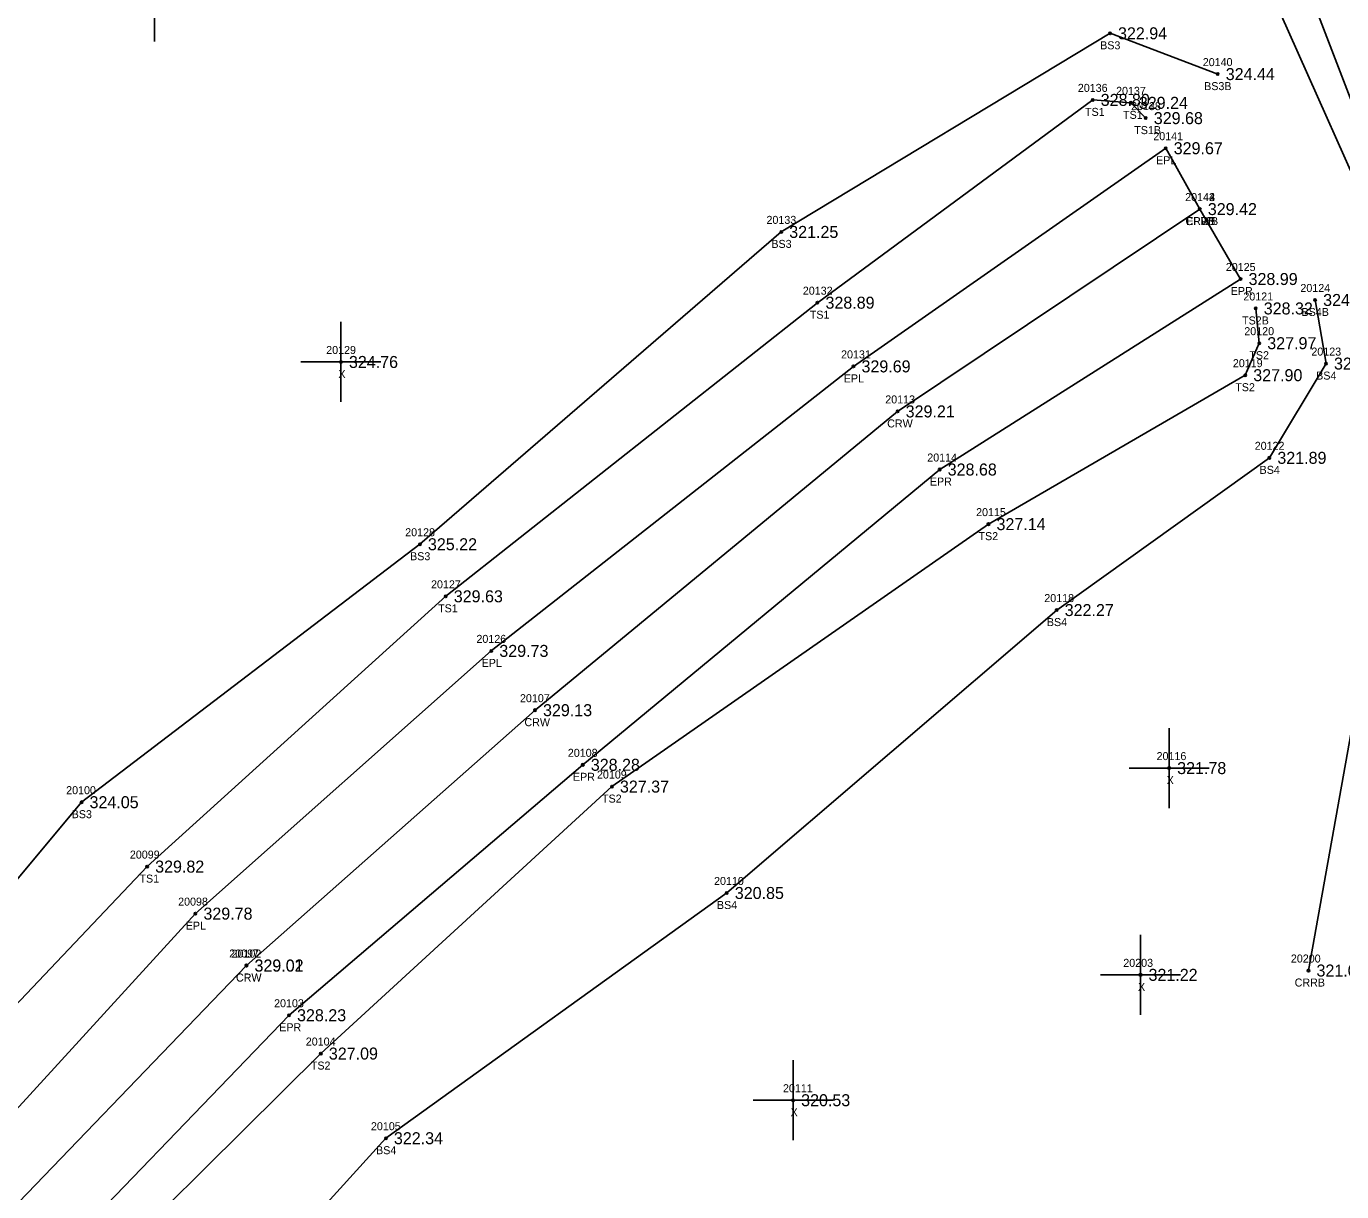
# Model space of a CAD drawing. Extents: x 2231109 to 2232328, y 1035718 to 1036919.
# Drawn here: x 2231394.8 to 2231559.2, y 1036302.1 to 1036447.8 of the extents above; entities that cross this region are included whole.
import ezdxf

# ---------------------------------------------------------------- set-up
doc = ezdxf.new("R2010")
doc.units = 0
for name, color, linetype in [('RD_DTM_BkLn1', 7, 'Continuous'), ('RD_DTM_BkLn2', 7, 'Continuous'), ('RD_DTM_BkLn_txCode', 7, 'Continuous'), ('RD_EX_H2O', 7, 'Continuous'), ('RD_EX_H2O_txCode', 7, 'Continuous'), ('RD_EX_Misc', 7, 'Continuous'), ('RD_EX_Misc_txCode', 7, 'Continuous'), ('RD_EX_Road', 7, 'Continuous'), ('RD_EX_Road_txCode', 7, 'Continuous'), ('RD_EX_TX_H2O_ELEV', 7, 'Continuous'), ('RD_EX_TX_Misc_ELEV', 7, 'Continuous'), ('RD_EX_TX_Road_ELEV', 7, 'Continuous'), ('RD_HC_Survey_ELEV', 7, 'Continuous'), ('RD_HC_Survey_txCode', 7, 'Continuous'), ('RD_SMD_Locator', 7, 'Continuous')]:
    doc.layers.add(name, color=color, linetype=linetype)

msp = doc.modelspace()

# ---------------------------------------------------------------- linework, layer by layer
at = {"layer": 'RD_DTM_BkLn1'}
msp.add_lwpolyline([(2231168.25, 1035745.18), (2231197.3, 1035848.59), (2231226.32, 1035944.04), (2231254.24, 1036037.31), (2231285.91, 1036129.66), (2231306.91, 1036176.17), (2231330.56, 1036216.58), (2231356.95, 1036257.36), (2231387.54, 1036294.26), (2231422.35, 1036330.42), (2231422.35, 1036330.4), (2231458.4, 1036362.33), (2231503.71, 1036399.67), (2231541.46, 1036424.96)], dxfattribs=at)
at = {"layer": 'RD_DTM_BkLn2'}
for points in [[(2231289.28, 1036185.01), (2231310.58, 1036229.41), (2231341.66, 1036269.31), (2231367.87, 1036310.22), (2231401.74, 1036350.83), (2231444.02, 1036383.07), (2231489.16, 1036422.11), (2231530.24, 1036446.93), (2231543.7, 1036441.83)], [(2231153.91, 1035749.54), (2231183.9, 1035852.41), (2231210.94, 1035948.08), (2231242.08, 1036041.75), (2231274.33, 1036134.79), (2231295.17, 1036181.88), (2231317.55, 1036225.12), (2231346.22, 1036265.16), (2231373.72, 1036304.6), (2231409.94, 1036342.78), (2231447.25, 1036376.56), (2231493.69, 1036413.26), (2231528.08, 1036438.61), (2231532.84, 1036438.24), (2231534.71, 1036436.33)], [(2231180.99, 1035741.83), (2231209.96, 1035844.49), (2231237.45, 1035939.8), (2231265.71, 1036032.03), (2231300.77, 1036123.1), (2231321.14, 1036169.41), (2231342.59, 1036208.04), (2231368.53, 1036247.79), (2231397.69, 1036285.75), (2231431.64, 1036319.41), (2231468.01, 1036352.78), (2231515.06, 1036385.58), (2231547.14, 1036404.2), (2231548.89, 1036408.2), (2231548.45, 1036412.54)], [(2231276.31, 1036031.77), (2231313.52, 1036118.16), (2231333.31, 1036164.6), (2231353.04, 1036201.77), (2231379.52, 1036238.63), (2231408.34, 1036274.21), (2231439.77, 1036308.83), (2231482.36, 1036339.48), (2231523.58, 1036374.84), (2231550.15, 1036393.87), (2231557.23, 1036405.65), (2231555.87, 1036413.6)]]:
    msp.add_lwpolyline(points, dxfattribs=at)
at = {"layer": 'RD_EX_H2O'}
for points in [[(2231554.2, 1036454.63), (2231567.2, 1036420.78), (2231573.56, 1036381.32), (2231561.13, 1036328.97)], [(2231550.29, 1036452.23), (2231565.49, 1036418.12), (2231564.98, 1036385.4), (2231555.04, 1036329.79)]]:
    msp.add_lwpolyline(points, dxfattribs=at)
at = {"layer": 'RD_EX_Misc'}
for p, q in [((2231410.85, 1036445.91), (2231410.85, 1036455.91)), ((2231434.15, 1036400.85), (2231434.15, 1036410.85)), ((2231429.15, 1036405.85), (2231439.15, 1036405.85)), ((2231537.63, 1036350.09), (2231537.63, 1036360.09)), ((2231532.63, 1036355.09), (2231542.63, 1036355.09)), ((2231534.05, 1036324.25), (2231534.05, 1036334.25)), ((2231529.05, 1036329.25), (2231539.05, 1036329.25)), ((2231490.65, 1036308.58), (2231490.65, 1036318.58)), ((2231485.65, 1036313.58), (2231495.65, 1036313.58))]:
    msp.add_line(p, q, dxfattribs=at)
at = {"layer": 'RD_EX_Road'}
for points in [[(2231158.42, 1035748.11), (2231188.37, 1035851.38), (2231216.59, 1035946.92), (2231244.77, 1036040.72), (2231278.59, 1036133.31), (2231299.55, 1036179.73), (2231323.11, 1036221.2), (2231350.7, 1036262.3), (2231381.59, 1036299.29), (2231415.97, 1036336.9), (2231452.94, 1036369.74), (2231498.19, 1036405.3), (2231537.2, 1036432.57), (2231541.46, 1036424.96)], [(2231176.43, 1035742.89), (2231206.61, 1035845.83), (2231234.19, 1035940.65), (2231261.92, 1036033.75), (2231294.68, 1036125.28), (2231316.11, 1036171.75), (2231338.19, 1036211.09), (2231363.83, 1036252.38), (2231394.08, 1036289.28), (2231427.67, 1036324.2), (2231464.37, 1036355.5), (2231508.96, 1036392.41), (2231546.55, 1036416.22), (2231541.46, 1036424.96)]]:
    msp.add_lwpolyline(points, dxfattribs=at)
at = {"layer": 'RD_SMD_Locator'}
for centre in [(2231530.24, 1036446.93), (2231543.7, 1036441.83), (2231528.08, 1036438.61), (2231532.84, 1036438.24), (2231534.71, 1036436.33), (2231537.2, 1036432.57), (2231541.46, 1036424.96), (2231541.46, 1036424.96), (2231541.46, 1036424.96), (2231489.16, 1036422.11), (2231546.55, 1036416.22), (2231493.69, 1036413.26), (2231548.45, 1036412.54), (2231555.87, 1036413.6), (2231548.89, 1036408.2), (2231434.15, 1036405.85), (2231557.23, 1036405.65), (2231498.19, 1036405.3), (2231547.14, 1036404.2), (2231503.71, 1036399.67), (2231550.15, 1036393.87), (2231508.96, 1036392.41), (2231515.06, 1036385.58), (2231444.02, 1036383.07), (2231447.25, 1036376.56), (2231523.58, 1036374.84), (2231452.94, 1036369.74), (2231458.4, 1036362.33), (2231464.37, 1036355.5), (2231537.63, 1036355.09), (2231468.01, 1036352.78), (2231401.74, 1036350.83), (2231409.94, 1036342.78), (2231482.36, 1036339.48), (2231415.97, 1036336.9), (2231422.35, 1036330.42), (2231422.35, 1036330.4), (2231534.05, 1036329.25), (2231555.04, 1036329.79), (2231427.67, 1036324.2), (2231431.64, 1036319.41), (2231490.65, 1036313.58), (2231439.77, 1036308.83)]:
    msp.add_circle(centre, 0.15, dxfattribs=at)

# ---------------------------------------------------------------- texts
at = {"layer": 'RD_DTM_BkLn_txCode'}
for s, p in [('BS3', (2231529.01, 1036444.93)), ('20140', (2231541.83, 1036442.83)), ('20136', (2231526.22, 1036439.61)), ('BS3B', (2231542, 1036439.83)), ('20137', (2231531, 1036439.24)), ('TS1', (2231527.12, 1036436.61)), ('TS1', (2231531.87, 1036436.24)), ('20138', (2231532.87, 1036437.33)), ('TS1B', (2231533.27, 1036434.33)), ('20133', (2231487.32, 1036423.11)), ('BS3', (2231487.93, 1036420.11)), ('20132', (2231491.86, 1036414.26)), ('20121', (2231546.9, 1036413.54)), ('20124', (2231554.03, 1036414.6)), ('BS4B', (2231554.17, 1036411.6)), ('TS1', (2231492.73, 1036411.26)), ('TS2B', (2231546.74, 1036410.54)), ('20120', (2231547.02, 1036409.2)), ('20123', (2231555.4, 1036406.65)), ('20119', (2231545.59, 1036405.2)), ('TS2', (2231547.65, 1036406.2)), ('BS4', (2231556, 1036403.65)), ('TS2', (2231545.89, 1036402.2)), ('20122', (2231548.32, 1036394.87)), ('BS4', (2231548.93, 1036391.87)), ('20115', (2231513.51, 1036386.58)), ('20128', (2231442.18, 1036384.07)), ('TS2', (2231513.81, 1036383.58)), ('BS3', (2231442.79, 1036381.07)), ('20127', (2231445.41, 1036377.56)), ('20118', (2231522.03, 1036375.84)), ('TS1', (2231446.29, 1036374.56)), ('BS4', (2231522.35, 1036372.84)), ('20109', (2231466.14, 1036353.78)), ('20100', (2231399.82, 1036351.83)), ('TS2', (2231466.77, 1036350.78)), ('BS3', (2231400.51, 1036348.83)), ('20099', (2231407.78, 1036343.78)), ('TS1', (2231408.98, 1036340.78)), ('20110', (2231480.77, 1036340.48)), ('BS4', (2231481.13, 1036337.48)), ('20104', (2231429.76, 1036320.41)), ('TS2', (2231430.39, 1036317.41)), ('20105', (2231437.9, 1036309.83)), ('BS4', (2231438.54, 1036306.83))]:
    msp.add_text(s, height=1, dxfattribs=at).set_placement(p)
at = {"layer": 'RD_EX_H2O_txCode'}
for s, p in [('20200', (2231552.84, 1036330.79)), ('CRRB', (2231553.31, 1036327.79))]:
    msp.add_text(s, height=1, dxfattribs=at).set_placement(p)
at = {"layer": 'RD_EX_Misc_txCode'}
for s, p in [('20129', (2231432.31, 1036406.85)), ('X', (2231433.83, 1036403.85)), ('20116', (2231536.06, 1036356.09)), ('X', (2231537.32, 1036353.09)), ('20203', (2231531.9, 1036330.25)), ('X', (2231533.74, 1036327.25)), ('20111', (2231489.38, 1036314.58)), ('X', (2231490.33, 1036311.58))]:
    msp.add_text(s, height=1, dxfattribs=at).set_placement(p)
at = {"layer": 'RD_EX_Road_txCode'}
for s, p in [('20141', (2231535.65, 1036433.57)), ('EPL', (2231535.99, 1036430.57)), ('20142', (2231539.63, 1036425.96)), ('20143', (2231539.63, 1036425.96)), ('EPRB', (2231539.76, 1036422.96)), ('EPLB', (2231539.78, 1036422.96)), ('20125', (2231544.71, 1036417.22)), ('EPR', (2231545.32, 1036414.22)), ('20131', (2231496.64, 1036406.3)), ('EPL', (2231496.98, 1036403.3)), ('20114', (2231507.41, 1036393.41)), ('EPR', (2231507.73, 1036390.41)), ('20126', (2231451.08, 1036370.74)), ('EPL', (2231451.73, 1036367.74)), ('20108', (2231462.5, 1036356.5)), ('EPR', (2231463.14, 1036353.5)), ('20098', (2231413.81, 1036337.9)), ('EPL', (2231414.76, 1036334.9)), ('20103', (2231425.8, 1036325.2)), ('EPR', (2231426.44, 1036322.2))]:
    msp.add_text(s, height=1, dxfattribs=at).set_placement(p)
at = {"layer": 'RD_EX_TX_H2O_ELEV'}
msp.add_text('321.00', height=1.5, dxfattribs=at).set_placement((2231556.04, 1036329.04))
at = {"layer": 'RD_EX_TX_Misc_ELEV'}
for s, p in [('322.94', (2231531.24, 1036446.18)), ('324.44', (2231544.7, 1036441.08)), ('328.80', (2231529.08, 1036437.86)), ('329.24', (2231533.84, 1036437.49)), ('329.68', (2231535.71, 1036435.58)), ('321.25', (2231490.16, 1036421.36)), ('328.89', (2231494.69, 1036412.51)), ('324.48', (2231556.87, 1036412.85)), ('328.32', (2231549.45, 1036411.79)), ('327.97', (2231549.89, 1036407.45)), ('324.76', (2231435.15, 1036405.1)), ('323.49', (2231558.23, 1036404.9)), ('327.90', (2231548.14, 1036403.45)), ('321.89', (2231551.15, 1036393.12)), ('327.14', (2231516.06, 1036384.83)), ('325.22', (2231445.02, 1036382.32)), ('329.63', (2231448.25, 1036375.81)), ('322.27', (2231524.58, 1036374.09)), ('321.78', (2231538.63, 1036354.34)), ('327.37', (2231469.01, 1036352.03)), ('324.05', (2231402.74, 1036350.08)), ('329.82', (2231410.94, 1036342.03)), ('320.85', (2231483.36, 1036338.73)), ('321.22', (2231535.05, 1036328.5)), ('327.09', (2231432.64, 1036318.66)), ('320.53', (2231491.65, 1036312.83)), ('322.34', (2231440.77, 1036308.08))]:
    msp.add_text(s, height=1.5, dxfattribs=at).set_placement(p)
at = {"layer": 'RD_EX_TX_Road_ELEV'}
for s, p in [('329.67', (2231538.2, 1036431.82)), ('329.42', (2231542.46, 1036424.21)), ('329.42', (2231542.46, 1036424.21)), ('328.99', (2231547.55, 1036415.47)), ('329.69', (2231499.19, 1036404.55)), ('328.68', (2231509.96, 1036391.66)), ('329.73', (2231453.94, 1036368.99)), ('328.28', (2231465.37, 1036354.75)), ('329.78', (2231416.97, 1036336.15)), ('328.23', (2231428.67, 1036323.45))]:
    msp.add_text(s, height=1.5, dxfattribs=at).set_placement(p)
at = {"layer": 'RD_HC_Survey_ELEV'}
for s, p in [('329.42', (2231542.46, 1036424.21)), ('329.21', (2231504.71, 1036398.92)), ('329.13', (2231459.4, 1036361.58)), ('329.02', (2231423.35, 1036329.67)), ('329.01', (2231423.35, 1036329.65))]:
    msp.add_text(s, height=1.5, dxfattribs=at).set_placement(p)
at = {"layer": 'RD_HC_Survey_txCode'}
for s, p in [('20144', (2231539.63, 1036425.96)), ('CRWB', (2231539.67, 1036422.96)), ('20113', (2231502.16, 1036400.67)), ('CRW', (2231502.4, 1036397.67)), ('20107', (2231456.52, 1036363.33)), ('CRW', (2231457.08, 1036360.33)), ('20097', (2231420.19, 1036331.42)), ('20102', (2231420.48, 1036331.4)), ('CRW', (2231421.03, 1036328.42)), ('CRW', (2231421.04, 1036328.4))]:
    msp.add_text(s, height=1, dxfattribs=at).set_placement(p)

doc.saveas('drawing.dxf')
